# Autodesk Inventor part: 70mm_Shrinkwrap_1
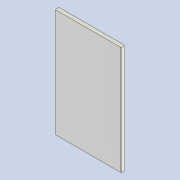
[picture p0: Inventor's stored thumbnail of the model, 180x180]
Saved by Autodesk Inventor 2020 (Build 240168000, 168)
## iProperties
Created: 2020-11
Part Number: 70mm_Shrinkwrap_1
Material: Generic
Document SubType Name: Modeling
Designer: Yolande
Density: 1 g/cm^3
Appearance: Default
description: 0:0:Lambdaboard 70mm White Mineral
manufacturer: 0:0:Lambdaboard T/A Rigifoam
model: 0:0:
url: 0:0:www.lambdaboard.com
Author: Yolande
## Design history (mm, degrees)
derived "70mm.iam"
body "Solid1"
node "Lambdaboard 70mm Mineral White.ipt:1" dims "d0" = 10
